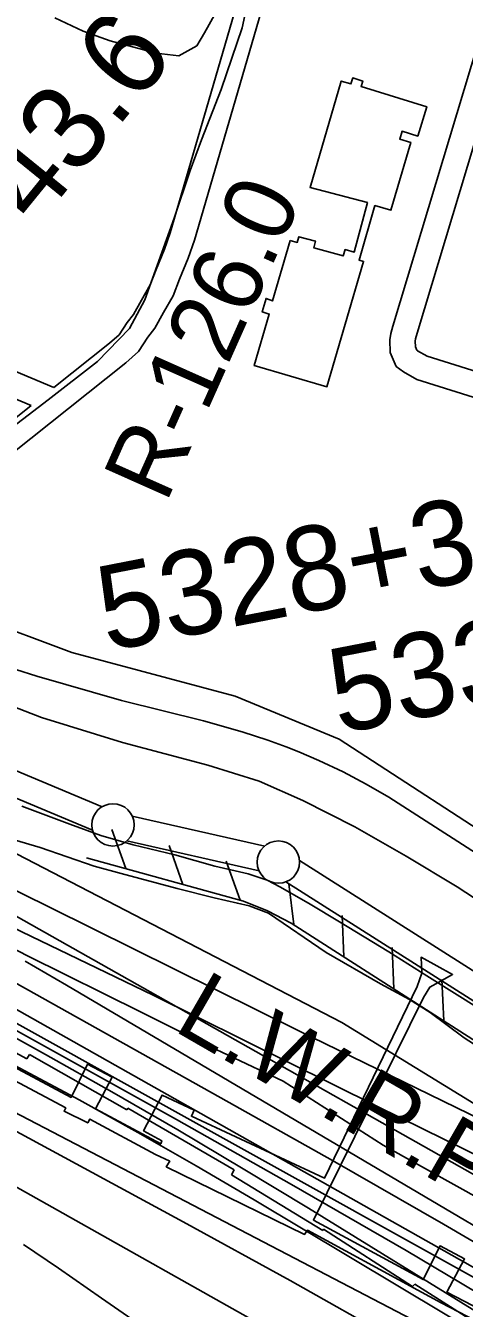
# Model space of a CAD drawing. Extents: x 3568792 to 3606828, y 529143 to 554785.
# Drawn here: x 3573273 to 3573791, y 544193 to 545708 of the extents above; entities that cross this region are included whole.
import ezdxf

# ---------------------------------------------------------------- set-up
doc = ezdxf.new("R2010")
doc.units = 0
for name, color, linetype in [('V-BLDG-OTLN', 7, 'Continuous'), ('V-CHAN-DOCK', 7, 'Continuous'), ('V-FLOD-BASE', 7, 'Continuous'), ('V-LEVE-TOET', 7, 'Continuous'), ('V-RIVR-EDGE', 7, 'Continuous'), ('V-RIVR-RANG-IDEN', 7, 'Continuous'), ('V-ROAD-CNTR', 7, 'Continuous'), ('V-RRAP-FSHR', 7, 'Continuous'), ('V-RRAP-RVMT', 7, 'Continuous'), ('V-SITE-OTLN', 7, 'Continuous'), ('V-SITE-VEGE', 7, 'Continuous'), ('V-SURV-IDEN', 7, 'Continuous'), ('V-SURV-LINE', 7, 'Continuous'), ('V-TOPO-DPTH', 7, 'Continuous'), ('V-TOPO-MAJR', 7, 'Continuous'), ('V-TOPO-MINR', 7, 'Continuous'), ('V-TOPO-WATR', 7, 'Continuous'), ('V-TOPO-WATR-IDEN', 7, 'Continuous'), ('V-UTIL-LINE', 7, 'Continuous')]:
    doc.layers.add(name, color=color, linetype=linetype)

msp = doc.modelspace()

# ---------------------------------------------------------------- linework, layer by layer
at = {"layer": 'V-BLDG-OTLN'}
msp.add_lwpolyline([(3573585.6, 545453.8), (3573593.8, 545451.8), (3573595.6, 545458.5), (3573615.4, 545453.2), (3573613.3, 545445.5), (3573648.1, 545435.8), (3573650.2, 545443.3), (3573661.1, 545440.4), (3573676.6, 545498.9), (3573608.9, 545516.6), (3573645.7, 545642.3), (3573657.1, 545638.8), (3573659.3, 545645.9), (3573671.1, 545642.3), (3573669.1, 545635.8), (3573746.7, 545612), (3573736.1, 545577.3), (3573717.5, 545583), (3573714.8, 545573.6), (3573727.8, 545569.8), (3573704.4, 545489.7), (3573685.5, 545495.2), (3573666.7, 545430.9), (3573672.1, 545429.3), (3573628.8, 545281.3), (3573543.1, 545306.4), (3573560.8, 545367.1), (3573552.5, 545369.6), (3573557.1, 545385.6), (3573564.7, 545382.7)], close=True, dxfattribs=at)
at = {"layer": 'V-CHAN-DOCK'}
for points in [[(3573241.4, 544487.8), (3573326.9, 544442.3), (3573346.5, 544481.4), (3573375.5, 544466.1), (3573355.7, 544428.9), (3573432.7, 544387.4), (3573434.1, 544390.8), (3573412.6, 544402.9), (3573434.4, 544445), (3573472.3, 544427.2), (3573468.9, 544419.9), (3573625.8, 544346.7), (3573735.3, 544573.2), (3573741, 544588.8), (3573740, 544607.7), (3573777.1, 544587.5), (3573750.1, 544572.5), (3573742.8, 544560.1), (3573612.9, 544297.4), (3573742.5, 544227.1), (3573762.3, 544266.9), (3573791.2, 544251.6), (3573770.3, 544212.2), (3573994.7, 544095.9)], [(3573988.6, 544082.9), (3573763.8, 544199.8), (3573736.3, 544214.5), (3573605.8, 544285.3), (3573602.5, 544280.4), (3573439.3, 544360.3), (3573443.3, 544366.9), (3573426.7, 544374.7), (3573349.1, 544416.6), (3573346.7, 544412.1), (3573318.7, 544426), (3573320.6, 544429.8), (3573235.4, 544475.2)]]:
    msp.add_lwpolyline(points, dxfattribs=at)
at = {"layer": 'V-FLOD-BASE'}
msp.add_lwpolyline([(3573268.8, 544786), (3573325.6, 544764.9), (3573362.1, 544751.3), (3573400.3, 544740.4), (3573449.4, 544728.7), (3573496.7, 544715.2), (3573535.8, 544706.1), (3573558.3, 544698.7), (3573574.1, 544690.3), (3573608.9, 544670.4), (3573643.6, 544649.6), (3573701.9, 544614.2), (3573746.6, 544585.8), (3573808.9, 544546.8)], dxfattribs=at)
at = {"layer": 'V-LEVE-TOET'}
for points in [[(3573207.5, 544923.4), (3573292, 544890.8), (3573387.6, 544861.2), (3573488.4, 544834.6), (3573548.8, 544815.8), (3573600.5, 544792.9), (3573661.6, 544761.8), (3573722.2, 544727.2), (3573782.5, 544690.8), (3573854.3, 544644.1)], [(3573198, 544764.4), (3573290.4, 544737.3), (3573354.3, 544715.4), (3573385.9, 544706.6), (3573452.2, 544689), (3573495.9, 544677.9), (3573523.3, 544671.4), (3573537.2, 544668.5), (3573559.8, 544659.6), (3573628.1, 544613.5), (3573692.1, 544576.5), (3573726.2, 544558), (3573750.6, 544542.4), (3573790.9, 544512.4), (3573862.2, 544466.4)]]:
    msp.add_lwpolyline(points, dxfattribs=at)
at = {"layer": 'V-RIVR-EDGE'}
msp.add_lwpolyline([(3573816.9, 544318.2), (3573695.2, 544385.9), (3573577.1, 544461.6), (3573490.8, 544502.3), (3573410.6, 544542.3), (3573275.4, 544609.4), (3573170.7, 544663.6), (3573072.2, 544726.9), (3572985.3, 544770.7), (3572927.2, 544812.5), (3572907.7, 544837.6), (3572872.8, 544858.6), (3572798.8, 544909), (3572708.8, 544952.1), (3572621.3, 544989.1), (3572511.7, 545015.7), (3572394.7, 545047.8), (3572308.4, 545067.7), (3572236.1, 545088.1)], dxfattribs=at)
at = {"layer": 'V-ROAD-CNTR'}
for points in [[(3574062.3, 547589.4), (3573888.3, 546988.4), (3573758.3, 546529.7), (3573562.5, 545870.8), (3573443.9, 545463.2), (3573437.2, 545443.7), (3573427.2, 545419.8), (3573420.1, 545401.7), (3573409.9, 545383.5), (3573400.5, 545366.8), (3573393.2, 545357.2), (3573383.6, 545342.7), (3573372.2, 545332.7), (3573306.5, 545280.3)], [(3573621, 545962.1), (3573591.3, 545862.3), (3573472.5, 545454.2), (3573465.3, 545433), (3573455, 545408.5), (3573447.3, 545388.8), (3573436, 545368.8), (3573425.7, 545350.3), (3573417.7, 545339.8), (3573406.5, 545322.8), (3573391.4, 545309.6), (3573234.8, 545184.7)], [(3573883.5, 545940.7), (3573706.5, 545352.9), (3573704.1, 545344.3), (3573703, 545336.9), (3573703.4, 545321.8), (3573710.6, 545305.4), (3573719.3, 545298.8), (3573734.9, 545289.9), (3574074.7, 545183.1), (3574097.9, 545178.1), (3574113.6, 545177.5), (3574128.5, 545178.4), (3574142.3, 545181.3), (3574249.3, 545245.9), (3574256.1, 545252.5), (3574265.5, 545261.9), (3574271.4, 545270.9), (3574278, 545281.4), (3574421, 545787.2)], [(3573912.4, 545932.5), (3573735.3, 545344.5), (3573733.5, 545337.9), (3573733, 545335), (3573733.2, 545328.5), (3573734.9, 545324.6), (3573735.9, 545323.9), (3573747, 545317.6), (3574082.4, 545212.2), (3574101.7, 545208), (3574113.2, 545207.5), (3574124.5, 545208.2), (3574131.2, 545209.7), (3574230.9, 545269.8), (3574235, 545273.9), (3574242.1, 545280.9), (3574246.1, 545287.1), (3574250.3, 545293.7), (3574392.1, 545795.4)], [(3573306.5, 545280.3), (3572820.4, 545484.5)], [(3573279.7, 545259), (3572808.8, 545456.8)], [(3573279.7, 545259), (3573184.4, 545182.9), (3573155.1, 545160.6), (3573142, 545144.5), (3573128.9, 545123.1), (3573083.5, 545047.4)], [(3573236.6, 544955.4), (3573286.7, 544939.7), (3573386.4, 544911), (3573483.2, 544887), (3573529, 544873.7), (3573559.3, 544864.2), (3573580.6, 544856.1), (3573595.8, 544850.2), (3573619.4, 544840.1), (3573648, 544826.5), (3573675.1, 544812), (3573701.8, 544796.8), (3573980.5, 544617.8)]]:
    msp.add_lwpolyline(points, dxfattribs=at)
at = {"layer": 'V-RRAP-FSHR'}
for p, q in [((3573391.5, 544712.4), (3573375.2, 544758.5)), ((3573458.9, 544693.7), (3573442.6, 544739.8)), ((3573526.4, 544675.1), (3573510.1, 544721.1)), ((3573590, 544646.2), (3573583.8, 544694.6)), ((3573648.8, 544608.1), (3573646.8, 544656.9)), ((3573707.7, 544570.3), (3573705.7, 544619.1)), ((3573766.6, 544532.6), (3573764.6, 544581.4))]:
    msp.add_line(p, q, dxfattribs=at)
msp.add_lwpolyline([(3573345.2, 544725.3), (3573530.3, 544674), (3573558.7, 544662.6), (3573586.8, 544647.9), (3573925.6, 544430.7), (3574142.6, 544294.6), (3574146.5, 544289), (3574146.9, 544275.4), (3574144.3, 544269.7), (3574139.4, 544258.4), (3574137.9, 544244.3), (3574138.8, 544230.7), (3574149.7, 544206.1), (3574161.6, 544199.9), (3574178.6, 544195.2), (3574195.5, 544196.1), (3574204.2, 544202.5), (3574212.4, 544213.5), (3574218.2, 544222.1), (3574225.1, 544228.4), (3574232.6, 544229), (3574273.4, 544209.9)], dxfattribs=at)
at = {"layer": 'V-RRAP-RVMT'}
for p, q in [((3573274.8, 544487.9), (3573157.4, 544551.1)), ((3573277.8, 544492.9), (3573274.8, 544487.9)), ((3573392.9, 544427.4), (3573277.8, 544492.9)), ((3573394.1, 544429.7), (3573392.9, 544427.4)), ((3573519.4, 544356.6), (3573394.1, 544429.7)), ((3573516.4, 544350.9), (3573519.4, 544356.6)), ((3573623.9, 544285), (3573516.4, 544350.9)), ((3573624.7, 544286.5), (3573623.9, 544285)), ((3573729.7, 544218.9), (3573624.7, 544286.5)), ((3573732.4, 544221.7), (3573729.7, 544218.9)), ((3573835.9, 544155.9), (3573732.4, 544221.7))]:
    msp.add_line(p, q, dxfattribs=at)
at = {"layer": 'V-SITE-OTLN'}
msp.add_lwpolyline([(3573862.5, 544722.6), (3573643.3, 544865.3), (3573520.6, 544916.1), (3573327.7, 544967.4), (3573216.3, 545009.2), (3573176.5, 545036.6), (3573117.5, 545077), (3573080.1, 545102.8), (3572938.6, 545210.5), (3572770.8, 545293.6), (3572732.9, 545315.6), (3572881.1, 545723.3)], dxfattribs=at)
at = {"layer": 'V-SITE-VEGE'}
for points in [[(3573540.4, 545758.4), (3573529, 545704.9), (3573516.8, 545669.3), (3573504, 545632.3), (3573480.8, 545572.8), (3573467.3, 545536.5), (3573448.7, 545480.4), (3573414, 545383.9), (3573395.8, 545350.2), (3573358, 545311), (3573299.8, 545265.7), (3573246.2, 545224.4)], [(3573307.7, 545716.8), (3573341.4, 545701.3), (3573373.1, 545689.7), (3573427.2, 545675.1), (3573454.2, 545672), (3573475.2, 545684), (3573484.3, 545699.3), (3573497.2, 545722.4)]]:
    msp.add_lwpolyline(points, dxfattribs=at)
at = {"layer": 'V-SURV-LINE'}
for points in [[(3573054.1, 544915.2), (3573363.8, 544785.5)], [(3573352.2, 544757.9), (3573042.5, 544887.5)], [(3573399.2, 544774.2), (3573555.4, 544739)], [(3573548.8, 544709.7), (3573392.6, 544745)], [(3573596.5, 544721.9), (3574289.7, 544281.5)], [(3574273.7, 544256.2), (3573580.4, 544696.6)]]:
    msp.add_lwpolyline(points, dxfattribs=at)
for centre in [(3573376.4, 544764), (3573571.6, 544720)]:
    msp.add_circle(centre, 25, dxfattribs=at)
at = {"layer": 'V-TOPO-DPTH'}
for points in [[(3574065.5, 544202.5), (3573222.1, 544678.6), (3573206.5, 544687.2), (3573190.8, 544695.7), (3573175, 544703.9), (3573159.1, 544711.9), (3573017.5, 544781.9), (3572930.3, 544824), (3572842.6, 544864.8), (3572754.1, 544904), (3572665, 544942), (3572214.4, 545129.1), (3572179.3, 545143.2), (3572143.9, 545156.7), (3572108.3, 545169.3), (3572072.4, 545181.3), (3572033.8, 545193.7), (3571978.3, 545210.8), (3571922.6, 545226.9), (3571866.4, 545241.6), (3571810, 545255.4), (3570994.2, 545443.6), (3570994.8, 545363.4)], [(3570994.8, 545363.4), (3570995, 545331.7), (3571053.7, 545317.8), (3571196.1, 545282.7), (3571338.1, 545246.1), (3571479.4, 545207.2), (3571620.4, 545166.7), (3572065.9, 545034.8), (3572082.6, 545029.6), (3572099.3, 545024.3), (3572115.8, 545018.6), (3572132.3, 545012.6), (3572360.8, 544927.8), (3572491, 544877.9), (3572620.4, 544826.3), (3572748.7, 544772.1), (3572876.3, 544716.1), (3573123.5, 544604.6), (3573134.6, 544599.4), (3573145.6, 544594.1), (3573156.4, 544588.4), (3573167.1, 544582.6), (3573827.9, 544215.5)], [(3573827.9, 544215.5), (3573167.1, 544582.6), (3573156.4, 544588.4), (3573145.6, 544594.1), (3573134.6, 544599.4), (3573123.5, 544604.6), (3572876.3, 544716.1), (3572748.7, 544772.1), (3572620.4, 544826.3), (3572491, 544877.9), (3572360.8, 544927.8), (3572132.3, 545012.6), (3572115.8, 545018.6), (3572099.3, 545024.3), (3572082.6, 545029.6), (3572065.9, 545034.8), (3571620.4, 545166.7), (3571479.4, 545207.2), (3571338.1, 545246.1), (3571196.1, 545282.7), (3571053.7, 545317.8), (3570995, 545331.7)], [(3570995.8, 545233.7), (3570996.1, 545194.7), (3571069, 545178.1), (3571147.9, 545158.7), (3571226.5, 545138.4), (3572043.6, 544920.6), (3572053, 544917.9), (3572062.5, 544915.2), (3572071.8, 544912.2), (3572081.1, 544909.1), (3572297.2, 544834.7), (3572414, 544792.9), (3572530.1, 544749.4), (3572645.2, 544703.2), (3572759.5, 544655.2), (3573081.6, 544515.6), (3573093.7, 544510.2), (3573105.7, 544504.6), (3573117.6, 544498.8), (3573129.4, 544492.8), (3573775.5, 544155.9), (3573852.4, 544115)], [(3570996.1, 545194.7), (3571069, 545178.1), (3571147.9, 545158.7), (3571226.5, 545138.4), (3572043.6, 544920.6), (3572053, 544917.9), (3572062.5, 544915.2), (3572071.8, 544912.2), (3572081.1, 544909.1), (3572297.2, 544834.7), (3572414, 544792.9), (3572530.1, 544749.4), (3572645.2, 544703.2), (3572759.5, 544655.2), (3573081.6, 544515.6), (3573093.7, 544510.2), (3573105.7, 544504.6), (3573117.6, 544498.8), (3573129.4, 544492.8), (3573775.5, 544155.9), (3573852.4, 544115)], [(3573897, 544216.4), (3573766.5, 544292.6), (3573635.3, 544367.6), (3573503.7, 544441.8), (3573220.2, 544600.2), (3573191.3, 544616.1), (3573162.2, 544631.6), (3573132.9, 544646.6), (3573103.5, 544661.4), (3573068.8, 544678.4), (3573021.7, 544701), (3572974.3, 544723.1), (3572926.6, 544744.5), (3572878.7, 544765.3), (3572237, 545038.9)], [(3572237, 545038.9), (3572878.7, 544765.3), (3572926.6, 544744.5), (3572974.3, 544723.1), (3573021.7, 544701), (3573068.8, 544678.4), (3573103.5, 544661.4), (3573132.9, 544646.6), (3573162.2, 544631.6), (3573191.3, 544616.1), (3573220.2, 544600.2), (3573503.7, 544441.8), (3573635.3, 544367.6), (3573766.5, 544292.6), (3573897, 544216.4)], [(3572227.4, 544948.9), (3572261.3, 544935.7), (3572295.2, 544922.3), (3573131.4, 544583.3), (3573135.3, 544581.6), (3573139.2, 544579.8), (3573143.1, 544577.9), (3573146.8, 544575.9), (3573296.7, 544493), (3573375, 544448.9), (3573452.9, 544404.1), (3573530.2, 544358.1), (3573607, 544311.4), (3574215.2, 543935.9)], [(3574215.2, 543935.9), (3573607, 544311.4), (3573530.2, 544358.1), (3573452.9, 544404.1), (3573375, 544448.9), (3573296.7, 544493), (3573146.8, 544575.9), (3573143.1, 544577.9), (3573139.2, 544579.8), (3573135.3, 544581.6), (3573131.4, 544583.3), (3572295.2, 544922.3), (3572261.3, 544935.7), (3572227.4, 544948.9)], [(3572121.5, 544928.3), (3572859.8, 544660.8), (3572904.8, 544644), (3572949.6, 544626.6), (3572994.1, 544608.4), (3573038.3, 544589.6), (3573056, 544581.9), (3573091, 544566.1), (3573125.8, 544549.8), (3573160.2, 544532.7), (3573194.4, 544515.1), (3573266.6, 544476.9), (3573336.4, 544439.2), (3573405.8, 544400.9), (3573474.5, 544361.4), (3573542.9, 544321.2), (3574219.3, 543916.4)], [(3574219.3, 543916.4), (3573542.9, 544321.2), (3573474.5, 544361.4), (3573405.8, 544400.9), (3573336.4, 544439.2), (3573266.6, 544476.9), (3573194.4, 544515.1), (3573160.2, 544532.7), (3573125.8, 544549.8), (3573091, 544566.1), (3573056, 544581.9), (3573038.3, 544589.6), (3572994.1, 544608.4), (3572949.6, 544626.6), (3572904.8, 544644), (3572859.8, 544660.8), (3572121.5, 544928.3)]]:
    msp.add_lwpolyline(points, dxfattribs=at)
at = {"layer": 'V-TOPO-MAJR'}
msp.add_lwpolyline([(3573835.2, 544082.7), (3573710.9, 544155.2), (3573585.5, 544226), (3573459.4, 544295.4), (3573108.5, 544485.4), (3573103.9, 544487.8), (3573099.2, 544490.1), (3573094.5, 544492.2), (3573089.7, 544494.1), (3572111.2, 544878.7)], dxfattribs=at)
at = {"layer": 'V-TOPO-MINR'}
for points in [[(3574065.5, 544202.5), (3573222.1, 544678.6), (3573206.5, 544687.2), (3573190.8, 544695.7), (3573175, 544703.9), (3573159.1, 544711.9), (3573017.5, 544781.9), (3572930.3, 544824), (3572842.6, 544864.8), (3572754.1, 544904), (3572665, 544942), (3572214.4, 545129.1), (3572179.3, 545143.2), (3572143.9, 545156.7), (3572108.3, 545169.3), (3572072.4, 545181.3), (3572033.8, 545193.7), (3571978.3, 545210.8), (3571922.6, 545226.9), (3571866.4, 545241.6), (3571810, 545255.4), (3570994.2, 545443.6)], [(3574182.7, 544026.5), (3573186.2, 544588.8), (3573168.9, 544598.3), (3573151.6, 544607.6), (3573134, 544616.5), (3573116.4, 544625.2), (3572977.5, 544692.2), (3572889.8, 544733.2), (3572801.6, 544772.9), (3572712.6, 544810.7), (3572622.9, 544847.1), (3572165.2, 545027.4), (3572136.5, 545038.4), (3572107.6, 545049), (3572078.5, 545059), (3572049.3, 545068.6), (3571926.8, 545107.4), (3571835.9, 545135.1), (3571744.7, 545161.5), (3571652.9, 545185.8), (3571560.7, 545208.8), (3570995, 545343.1)], [(3573827.9, 544215.5), (3573167.1, 544582.6), (3573156.4, 544588.4), (3573145.6, 544594.1), (3573134.6, 544599.4), (3573123.5, 544604.6), (3572876.3, 544716.1), (3572748.7, 544772.1), (3572620.4, 544826.3), (3572491, 544877.9), (3572360.8, 544927.8), (3572132.3, 545012.6), (3572115.8, 545018.6), (3572099.3, 545024.3), (3572082.6, 545029.6), (3572065.9, 545034.8), (3571620.4, 545166.7), (3571479.4, 545207.2), (3571338.1, 545246.1), (3571196.1, 545282.7), (3571053.7, 545317.8), (3570995, 545331.7)], [(3573856.3, 544181.4), (3573722.3, 544261.4), (3573587.2, 544339.4), (3573451.4, 544416.1), (3573157, 544579.3), (3573149.7, 544583.2), (3573142.4, 544586.9), (3573134.9, 544590.4), (3573127.4, 544593.7), (3572595.8, 544818.6), (3572513.2, 544852.8), (3572430.1, 544885.9), (3572346.5, 544917.7), (3572262.5, 544948.5), (3572111, 545002.7), (3572102.5, 545005.6), (3572093.9, 545008.4), (3572085.3, 545011.1), (3572076.7, 545013.6), (3571011.8, 545312.8), (3570995.2, 545317.3)], [(3573852.4, 544115), (3573775.5, 544155.9), (3573129.4, 544492.8), (3573117.6, 544498.8), (3573105.7, 544504.6), (3573093.7, 544510.2), (3573081.6, 544515.6), (3572759.5, 544655.2), (3572645.2, 544703.2), (3572530.1, 544749.4), (3572414, 544792.9), (3572297.2, 544834.7), (3572081.1, 544909.1), (3572071.8, 544912.2), (3572062.5, 544915.2), (3572053, 544917.9), (3572043.6, 544920.6), (3571226.5, 545138.4), (3571147.9, 545158.7), (3571069, 545178.1), (3570996.1, 545194.7)], [(3574215.2, 543935.9), (3573607, 544311.4), (3573530.2, 544358.1), (3573452.9, 544404.1), (3573375, 544448.9), (3573296.7, 544493), (3573146.8, 544575.9), (3573143.1, 544577.9), (3573139.2, 544579.8), (3573135.3, 544581.6), (3573131.4, 544583.3), (3572295.2, 544922.3), (3572261.3, 544935.7), (3572227.4, 544948.9)], [(3574219.3, 543916.4), (3573542.9, 544321.2), (3573474.5, 544361.4), (3573405.8, 544400.9), (3573336.4, 544439.2), (3573266.6, 544476.9), (3573194.4, 544515.1), (3573160.2, 544532.7), (3573125.8, 544549.8), (3573091, 544566.1), (3573056, 544581.9), (3573038.3, 544589.6), (3572994.1, 544608.4), (3572949.6, 544626.6), (3572904.8, 544644), (3572859.8, 544660.8), (3572121.5, 544928.3)], [(3573809.5, 544027.9), (3573735.9, 544069.9), (3573126, 544413.2), (3573101.4, 544426.6), (3573076.6, 544439.5), (3573051.5, 544451.7), (3573026.1, 544463.5), (3572921.5, 544510.2), (3572843.1, 544543.8), (3572764.2, 544575.8), (3572684.3, 544605.6), (3572603.9, 544633.8), (3572054.6, 544817.3)], [(3574321.5, 544116.1), (3573646.3, 544530.5), (3573092.3, 544817.9)], [(3574270.6, 544014.2), (3573321.5, 544574.6), (3573297.2, 544588.9), (3573272.7, 544603)], [(3573271, 544268.5), (3573312.2, 544240.6), (3573363, 544205.1), (3573429.3, 544159)]]:
    msp.add_lwpolyline(points, dxfattribs=at)
at = {"layer": 'V-TOPO-WATR'}
msp.add_lwpolyline([(3573897, 544216.4), (3573766.5, 544292.6), (3573635.3, 544367.6), (3573503.7, 544441.8), (3573220.2, 544600.2), (3573191.3, 544616.1), (3573162.2, 544631.6), (3573132.9, 544646.6), (3573103.5, 544661.4), (3573068.8, 544678.4), (3573021.7, 544701), (3572974.3, 544723.1), (3572926.6, 544744.5), (3572878.7, 544765.3), (3572237, 545038.9)], dxfattribs=at)
at = {"layer": 'V-UTIL-LINE'}
msp.add_lwpolyline([(3572965.6, 544785.3), (3573179.7, 544680.6), (3573423.7, 544562.9), (3573688.4, 544431.4), (3573926.6, 544314.4), (3574065.1, 544250), (3574072.6, 544264.8), (3574078.8, 544277.2), (3573827.3, 544408), (3573595.7, 544520.9), (3573303, 544666.1), (3573064.8, 544783.8), (3572986.8, 544820.4)], dxfattribs=at)

# ---------------------------------------------------------------- texts
at = {"layer": 'V-RIVR-RANG-IDEN'}
msp.add_text('R-126.0', height=83, rotation=65.984, dxfattribs=at).set_placement((3573438.9, 545142.5))
at = {"layer": 'V-SURV-IDEN'}
for s, rotation, p in [('5322+43.6', 50.8887, (3573049.5, 545178)), ('5328+34.6', 11.0178, (3573369.2, 544968.7)), ('5330+34.7', 11.0087, (3573642.4, 544871.2))]:
    msp.add_text(s, height=100, rotation=rotation, dxfattribs=at).set_placement(p)
at = {"layer": 'V-TOPO-WATR-IDEN'}
msp.add_text('L.W.R.P.', height=83, rotation=330.019, dxfattribs=at).set_placement((3573446.1, 544522.2))

doc.saveas('drawing.dxf')
